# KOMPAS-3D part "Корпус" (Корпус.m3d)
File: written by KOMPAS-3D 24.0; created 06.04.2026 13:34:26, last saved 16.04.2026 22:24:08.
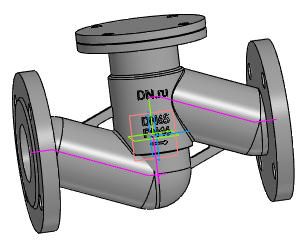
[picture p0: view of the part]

Document properties: Автор: R2D2; Полное имя файла: E:\Работа\Зайцев\VSO3131M-F-S Клапан запорный DN.ru Ду15-100 Ру16\DN65\исходные материалы\Корпус.m3d

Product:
- Body: Труба / Нестандартная труба / L = 148.6 мм  | qty 1
    Материал: Нестандартная труба (density 7856 kg/m3)
    Масса: 22.548898
    Раздел спецификации: Детали
    Примечание: 5,16 кг
    additional columns: Pipeline; 0.075; 0; 0; 0.002; 0.14858; true; 0.04
- Body: Труба / Нестандартная труба / L = 190 мм  | qty 1
    Материал: Нестандартная труба (density 7856 kg/m3)
    Масса: 22.548898
    Раздел спецификации: Детали
    Примечание: 6,59 кг
    additional columns: Pipeline; 0.075; 0; 0; 0.002; 0.18995; true; 0.04
- Body: Тело 4  | qty 1
    Материал: Нестандартная труба (density 7856 kg/m3)
    Масса: 22.548898
- Body: Тело 5  | qty 1
    Материал: Нестандартная труба (density 7856 kg/m3)
    Масса: 22.548898
- Body: Тело 8  | qty 1
    Материал: Нестандартная труба (density 7856 kg/m3)
    Масса: 22.548898
- Body: Тело 9  | qty 1
    Материал: Нестандартная труба (density 7856 kg/m3)
    Масса: 22.548898
- Part/product: Корпус
    Масса: 6.9

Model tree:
1. Труба
2. Труба:1  (labels: {F703FF30-5BE6-4673-A7F1-8EDA1BE1E2D1}; SHAPEOBJECT3D_ATTR_BUTT; SHAPEOBJECT3D_ATTR_VALID; SHAPEOBJECT3D_ATTR_BUTT_AREA)
     PIPE_R = 7
3. Труба:2  (labels: {F703FF30-5BE6-4673-A7F1-8EDA1BE1E2D1}; SHAPEOBJECT3D_ATTR_BUTT; SHAPEOBJECT3D_ATTR_VALID; SHAPEOBJECT3D_ATTR_BUTT_AREA)
     PIPE_R = 5
4. Колонна
5. Элемент выдавливания:1
     Смещение 1 = -1; Смещение 2 = -5
6. Скругление:17  (with: Ребро.Элемент выдавливания:1)
     Радиус = 1
7. Скругление:18  (with: Ребро.Элемент выдавливания:1)
8. Скругление:24  (with: Ребро.Элемент выдавливания:1)
     Радиус = 0.5
9. Элемент выдавливания:2
     Расстояние 1 = 6
10. Скругление:19  (with: Ребро.Элемент выдавливания:2)
     Радиус = 2
11. Эскиз:4  (with: Грань.Элемент выдавливания:1)
12. Элемент выдавливания:3
     Расстояние 1 = 32.5
13. Скругление:21  (with: Ребро.Элемент выдавливания:3)
14. ОТЛИВКА
15. Скругление:6  (with: Грань.Элемент выдавливания:1)
     Радиус = 2
16. Элемент выдавливания:6  (with: Грань.Элемент выдавливания:1)
     Смещение 1 = 4
17. ЛЕЙБЛ
18. Элемент выдавливания:7  (with: Грань.Элемент выдавливания:1)
     Расстояние 1 = 43.4997; Смещение 1 = 1
19. Фланец верх  (with: Ребро.Элемент выдавливания:3)
20. Элемент вращения:2
     Угол 1 = 360
21. Эскиз:12  (with: Грань.Элемент вращения:2)
22. Элемент выдавливания:9  (with: Грань.Элемент вращения:2)
     Расстояние 2 = 20
23. Массив по концентрической сетке:1  (with: Элемент выдавливания:9, Эскиз:12, Грань.Элемент вращения:2)  (4 pattern instances)
     Шаг 2 = 360
24. Фланец
25. Элемент вращения:1
     Угол 1 = 360
26. отвертие во фланце  (with: Грань.Элемент вращения:1)
27. Элемент выдавливания:8
28. Массив по концентрической сетке:2  (with: Элемент выдавливания:8, Эскиз:10, Грань.Элемент вращения:1)  (4 pattern instances)
     Шаг 2 = 360
29. Зеркальный массив:1
30. Экземпляр ( 1 )
31. Экземпляр ( 2 )  (with: Элемент вращения:1, Массив по концентрической сетке:2, Экземпляр ( 1 ), Элемент выдавливания:8)
32. Экземпляр ( 3 )  (with: Элемент выдавливания:8)
33. Экземпляр ( 4 )  (with: Элемент выдавливания:8)
34. Скругление:25  (with: Ребро.Элемент вращения:2)
     Радиус = 2
35. Скругление:26
     Радиус = 2

Expressions: DS/2+3; D1/2; DN/2; DS-v977*4; LL/2; D1-v1234*2; D/2+15
Referenced files in C:\Program Files\ASCON\KOMPAS-3D v24\Libs\Pipeline\: StylesTemplate.a3d, TemplateHPH, InsulationStylesTemplate.a3d, Insulation
Referenced files in C:\Program Files\ASCON\KOMPAS-3D v24\Templates\: Констр. чертеж А3 гориз. перв. лист.cdt
Referenced files in E:\Работа\Зайцев\VSO3131M-F-S Клапан запорный DN.ru Ду15-100 Ру40\DN20\исходные материалы\: 
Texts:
  Отводы ГОСТ 17375-2001
  Констр. чертеж А3 гориз. перв. лист.cdt
  GOST 26.020 Pr3
  var3D
  смещение колонны вниз
  LL-10
  DN+10
  Труба / Нестандартная труба / L = %s мм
